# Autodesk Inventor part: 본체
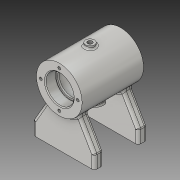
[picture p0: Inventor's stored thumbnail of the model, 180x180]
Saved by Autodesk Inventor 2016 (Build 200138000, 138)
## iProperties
Created: 2018-05
Part Number: 본체
Material: 알루미늄 6061
Document SubType Name: Modeling
Designer: Administrator
Density: 2.7 g/cm^3
Appearance: 알루미늄 - 평지
Mass: 319.096 g
Surface Area: 369.089 cm^2
Volume: 118.184 cm^3
Author: Administrator
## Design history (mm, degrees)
node "작업 평면1"
sketch "스케치1"
  geometry: L1 (6.132, 65)-(-6.132, 65); L2 (-35, 0)-(35, 0); L3 (6.132, 65)-(35, 15); L4 (35, 15)-(35, 0); L5 (-6.132, 65)-(-35, 15); L6 (-35, 15)-(-35, 0); 2 further points
  constraints: 12 end point, 1 coincident, 1 horizontal, 1 midpoint, 1 parallel, 1 perpendicular, 1 vertical
  dimensions: "d1" = 70 distance of L2.start L2.end; "d4" = 30 deg angle of L4 L3; "d5" = 30 deg angle of L6 L5; "d6" = 65 distance between parallel lines of L2 L1; "d7" = 15 distance of L5.end L2.start; "d8" = 15 distance of L3.end L2.end
extrude "돌출1" new body sketch "스케치1" distance "d9" = 10; taper "d10" = 0 deg
sketch "스케치2"
  geometry: L1 (35, 0)-(-35, 0) reference; C1 r 26 at (0, 65); 2 further points
  constraints: 1 centre point, 1 midpoint, 1 vertical alignment
  dimensions: "d11" = 65 distance from line of L1 C1.centre; "d12" = 52 diameter of C1
extrude "돌출2" join sketch "스케치2" distance "d13" = 35; taper "d14" = 0 deg
sketch "스케치3"
  geometry: L1 (35, 39)-(35, 91) reference; L2 (35, 65)-(0, 65); L3 (0, 91)-(0, 39) reference; L4 (21, 86)-(0, 86); L5 (21, 86)-(21, 79); L6 (21, 79)-(23, 79); L7 (23, 79)-(23, 81); L8 (23, 81)-(35, 81); L9 (35, 81)-(35, 65); L10 (0, 86)-(0, 65); 1 further point
  constraints: 16 end point, 4 perpendicular, 2 point on line, 1 collinear, 1 horizontal, 1 midpoint, 1 vertical
  dimensions: "d15" = 42 diameter of L4 L2; "d16" = 28 diameter of L6 L2; "d17" = 32 diameter of L8 L2; "d18" = 21 distance of L4.start L4.end; "d19" = 12 distance of L7.end L8.end
revolve "회전1" sketch "스케치3" stored, may be unused: angle "d20" = 90 deg
sketch "스케치4"
  geometry: C1 r 16 at (0, 0) reference; 2 further points
  constraints: 1 vertical alignment
  dimensions: "d21" = 21 distance of C1.centre point (0, -21)
hole "구멍1" sketch "스케치4" at (0, -21) diameter "d22" = 3.242; stored, may be unused: countersink angle "d26" = 90 deg, drill point angle "d28" = 118 deg; dims "d23" = 8, "d24" = 4, "d25" = 2, "d27" = 10
node "작업 평면2"
sketch "스케치5"
  geometry: C1 r 5 at (0, 0); 1 further point
  constraints: 1 centre point, 1 coincident
  dimensions: "d33" = 10 diameter of C1
extrude "돌출3" join sketch "스케치5" stored distance "d34" = 35; taper "d35" = 0 deg
hole "구멍2" diameter "d38" = 5.188; stored, may be unused: countersink angle "d42" = 90 deg, drill point angle "d44" = 118 deg; dims "d36" = 10, "d37" = 10, "d39" = 12, "d40" = 4, "d41" = 2, "d43" = 16
sketch "스케치6"
  geometry: L1 (0, 65)-(-9.919, 37.749); L2 (-9.919, 37.749)-(-15.557, 39.801); L3 (-15.557, 39.801)-(-13.163, 46.379); L4 (-13.163, 46.379)-(-7.524, 44.327); L5 (0, 65)-(0, 33.027); C1 r 14 at (0, 65) reference; 1 further point
  constraints: 10 end point, 2 perpendicular, 1 parallel, 1 point on line, 1 vertical
  dimensions: "d45" = 29 distance of L1.start L1.end; "d46" = 6 distance of L1.end L2.end; "d47" = 20 deg angle of L5 L1; "d48" = 7 distance of L2.end L3.end
revolve "회전2" sketch "스케치6" stored, may be unused: angle "d49" = 90 deg
hole "구멍3" diameter "d52" = 5.188; stored, may be unused: countersink angle "d56" = 90 deg, drill point angle "d58" = 118 deg; dims "d53" = 12, "d54" = 4, "d55" = 2, "d57" = 16, "d81" = 10, "d82" = 10
fillet "모깎기1" dims "d59" = 2
fillet "모깎기2" dims "d60" = 0.3
fillet "모깎기3" dims "d61" = 3
fillet "모깎기4" dims "d62" = 3
fillet "모깎기5" dims "d63" = 3
fillet "모깎기6" dims "d64" = 3
chamfer "모따기1" distance "d65" = 1; stored, may be unused: second distance "d66" = 2, angle "d67" = 45 deg
sketch "스케치8"
  geometry: L1 (64, 0)-(0, 0) reference; 2 further points
  dimensions: "d72" = 20 horizontal distance of point (32, -20) point (12, 5); "d73" = 5 distance from line of L1 point (12, 5)
hole "구멍4" sketch "스케치8" at (12, 5) diameter "d74" = 4.134; stored, may be unused: countersink angle "d78" = 90 deg, drill point angle "d80" = 118 deg; dims "d75" = 8, "d76" = 4, "d77" = 2, "d79" = 10
node "작업 평면4"
sketch "스케치9"
  geometry: L1 (35, 26)-(-35, 26) reference; L2 (-35, 26)-(-35, -26) reference; 2 further points
  constraints: 1 other
  dimensions: "d83" = 26 distance from line of L1 point (1, 0); "d84" = 36 distance from line of L2 point (1, 0)
feature "엠보싱2" sketch "스케치9" dims "d1" = 70, "d4" = 30 deg, "d5" = 30 deg, "d6" = 65, "d7" = 15, "d8" = 15, "d85" = 0.5, "d86" = 0
sketch "스케치10"
  geometry: L1 (0, 36.003)-(46.595, 36.003); L2 (46.595, 36.003)-(46.595, -68.588); L3 (46.595, -68.588)-(0, -68.588); L4 (0, -68.588)-(0, 36.003); 1 further point
  constraints: 8 end point, 2 parallel, 1 horizontal, 1 perpendicular
extrude "돌출4" cut sketch "스케치10" stored distance "d87" = 0; taper "d88" = 0 deg
node "솔리드1"
mirror "대칭1"
pattern_circular "원형 패턴1" dims angle "d30" = 360 deg
mirror "대칭2"
mirror "대칭3"
mirror "대칭4"
other parameters: "d32" = 94
